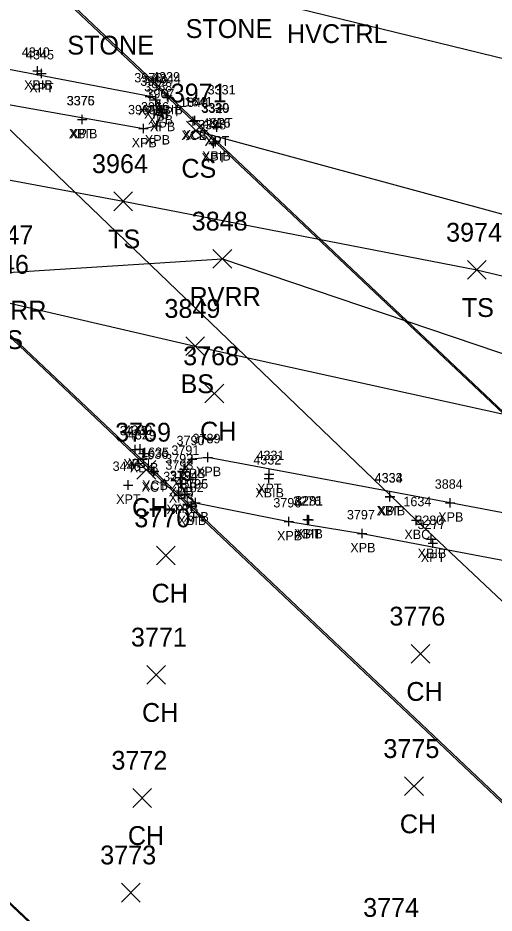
# Model space of a CAD drawing. Extents: x 1647574 to 1652703, y 212895 to 228670.
# Drawn here: x 1648896.4 to 1648947, y 227216.4 to 227311.5 of the extents above; entities that cross this region are included whole.
import ezdxf

# ---------------------------------------------------------------- set-up
doc = ezdxf.new("R2010")
doc.units = 0
for name, color, linetype in [('B_A', 7, 'Continuous'), ('B_I', 7, 'Continuous'), ('B_TIC', 7, 'Continuous'), ('BDC', 7, 'Continuous'), ('BELB', 7, 'Continuous'), ('BSUBM', 7, 'Continuous'), ('C_A', 7, 'Continuous'), ('L_A', 7, 'Continuous'), ('L_I', 7, 'Continuous'), ('L_TIC', 7, 'Continuous'), ('LASF', 7, 'Continuous'), ('LAWE', 7, 'Continuous'), ('LELB', 7, 'Continuous')]:
    doc.layers.add(name, color=color, linetype=linetype)

msp = doc.modelspace()

# ---------------------------------------------------------------- linework, layer by layer
at = {"layer": 'B_TIC'}
for p, q in [((1648898.446, 227305.876), (1648898.522, 227305.876)), ((1648898.857, 227305.593), (1648898.932, 227305.593)), ((1648910.416, 227303.154), (1648910.492, 227303.154)), ((1648911.039, 227302.784), (1648911.114, 227302.784)), ((1648912.274, 227303.242), (1648912.349, 227303.242)), ((1648912.349, 227303.053), (1648912.424, 227303.053)), ((1648911.454, 227302.179), (1648911.53, 227302.179)), ((1648917.888, 227301.873), (1648917.964, 227301.873)), ((1648903.197, 227300.71), (1648903.272, 227300.71)), ((1648903.197, 227300.71), (1648903.272, 227300.71)), ((1648911.684, 227301.467), (1648911.759, 227301.467)), ((1648909.729, 227299.757), (1648909.804, 227299.757)), ((1648911.134, 227300.053), (1648911.21, 227300.053)), ((1648915.01, 227300.535), (1648915.086, 227300.535)), ((1648915.18, 227300.61), (1648915.255, 227300.61)), ((1648917.521, 227299.968), (1648917.596, 227299.968)), ((1648917.529, 227299.911), (1648917.605, 227299.911)), ((1648917.163, 227298.161), (1648917.238, 227298.161)), ((1648917.379, 227298.344), (1648917.455, 227298.344)), ((1648908.838, 227265.651), (1648908.913, 227265.651)), ((1648909.349, 227265.697), (1648909.425, 227265.697)), ((1648909.695, 227265.208), (1648909.77, 227265.208)), ((1648914.907, 227264.6), (1648914.983, 227264.6)), ((1648916.569, 227264.809), (1648916.644, 227264.809)), ((1648914.034, 227263.572), (1648914.109, 227263.572)), ((1648910.793, 227263.155), (1648910.868, 227263.155)), ((1648910.839, 227263.351), (1648910.915, 227263.351)), ((1648913.66, 227262.668), (1648913.735, 227262.668)), ((1648923.086, 227263.025), (1648923.161, 227263.025)), ((1648908.097, 227261.869), (1648908.173, 227261.869)), ((1648913.679, 227261.994), (1648913.754, 227261.994)), ((1648923.04, 227262.55), (1648923.115, 227262.55)), ((1648913.445, 227260.778), (1648913.521, 227260.778)), ((1648914.149, 227260.891), (1648914.225, 227260.891)), ((1648915.258, 227259.994), (1648915.333, 227259.994)), ((1648935.938, 227260.651), (1648936.013, 227260.651)), ((1648935.941, 227260.624), (1648936.016, 227260.624)), ((1648942.333, 227259.976), (1648942.409, 227259.976)), ((1648914.776, 227259.618), (1648914.851, 227259.618)), ((1648925.19, 227257.988), (1648925.265, 227257.988)), ((1648927.18, 227258.193), (1648927.256, 227258.193)), ((1648927.3, 227258.172), (1648927.375, 227258.172)), ((1648938.736, 227258.119), (1648938.812, 227258.119)), ((1648932.986, 227256.718), (1648933.061, 227256.718)), ((1648940.311, 227256.124), (1648940.386, 227256.124)), ((1648940.497, 227255.688), (1648940.573, 227255.688))]:
    msp.add_line(p, q, dxfattribs=at)
for points in [[(1648898.443, 227305.376), (1648898.443, 227306.376)], [(1648897.943, 227305.876), (1648898.943, 227305.876)], [(1648898.353, 227305.593), (1648899.353, 227305.593)], [(1648898.853, 227305.093), (1648898.853, 227306.093)], [(1648910.413, 227302.654), (1648910.413, 227303.654)], [(1648912.27, 227302.742), (1648912.27, 227303.742)], [(1648912.345, 227302.553), (1648912.345, 227303.553)], [(1648909.913, 227303.154), (1648910.913, 227303.154)], [(1648910.535, 227302.784), (1648911.535, 227302.784)], [(1648911.035, 227302.284), (1648911.035, 227303.284)], [(1648911.451, 227301.679), (1648911.451, 227302.679)], [(1648911.77, 227303.242), (1648912.77, 227303.242)], [(1648911.845, 227303.053), (1648912.845, 227303.053)], [(1648910.951, 227302.179), (1648911.951, 227302.179)], [(1648911.68, 227300.967), (1648911.68, 227301.967)], [(1648917.385, 227301.873), (1648918.385, 227301.873)], [(1648917.885, 227301.373), (1648917.885, 227302.373)], [(1648902.693, 227300.71), (1648903.693, 227300.71)], [(1648902.693, 227300.71), (1648903.693, 227300.71)], [(1648903.193, 227300.21), (1648903.193, 227301.21)], [(1648903.193, 227300.21), (1648903.193, 227301.21)], [(1648911.18, 227301.467), (1648912.18, 227301.467)], [(1648915.007, 227300.035), (1648915.007, 227301.035)], [(1648915.176, 227300.11), (1648915.176, 227301.11)], [(1648909.225, 227299.757), (1648910.225, 227299.757)], [(1648909.725, 227299.257), (1648909.725, 227300.257)], [(1648910.631, 227300.053), (1648911.631, 227300.053)], [(1648911.131, 227299.553), (1648911.131, 227300.553)], [(1648914.507, 227300.535), (1648915.507, 227300.535)], [(1648914.676, 227300.61), (1648915.676, 227300.61)], [(1648917.018, 227299.968), (1648918.018, 227299.968)], [(1648917.026, 227299.911), (1648918.026, 227299.911)], [(1648917.518, 227299.468), (1648917.518, 227300.468)], [(1648917.526, 227299.411), (1648917.526, 227300.411)], [(1648917.376, 227297.844), (1648917.376, 227298.844)], [(1648916.659, 227298.161), (1648917.659, 227298.161)], [(1648916.876, 227298.344), (1648917.876, 227298.344)], [(1648917.159, 227297.661), (1648917.159, 227298.661)], [(1648908.334, 227265.651), (1648909.334, 227265.651)], [(1648908.834, 227265.151), (1648908.834, 227266.151)], [(1648908.846, 227265.697), (1648909.846, 227265.697)], [(1648909.346, 227265.197), (1648909.346, 227266.197)], [(1648909.691, 227264.708), (1648909.691, 227265.708)], [(1648909.191, 227265.208), (1648910.191, 227265.208)], [(1648914.404, 227264.6), (1648915.404, 227264.6)], [(1648914.904, 227264.1), (1648914.904, 227265.1)], [(1648916.066, 227264.809), (1648917.066, 227264.809)], [(1648916.566, 227264.309), (1648916.566, 227265.309)], [(1648910.789, 227262.655), (1648910.789, 227263.655)], [(1648910.836, 227262.851), (1648910.836, 227263.851)], [(1648913.53, 227263.572), (1648914.53, 227263.572)], [(1648914.03, 227263.072), (1648914.03, 227264.072)], [(1648923.082, 227262.525), (1648923.082, 227263.525)], [(1648910.289, 227263.155), (1648911.289, 227263.155)], [(1648910.336, 227263.351), (1648911.336, 227263.351)], [(1648913.156, 227262.668), (1648914.156, 227262.668)], [(1648913.656, 227262.168), (1648913.656, 227263.168)], [(1648922.582, 227263.025), (1648923.582, 227263.025)], [(1648923.036, 227262.05), (1648923.036, 227263.05)], [(1648907.594, 227261.869), (1648908.594, 227261.869)], [(1648908.094, 227261.369), (1648908.094, 227262.369)], [(1648913.175, 227261.994), (1648914.175, 227261.994)], [(1648913.675, 227261.494), (1648913.675, 227262.494)], [(1648922.536, 227262.55), (1648923.536, 227262.55)], [(1648912.942, 227260.778), (1648913.942, 227260.778)], [(1648913.442, 227260.278), (1648913.442, 227261.278)], [(1648913.646, 227260.891), (1648914.646, 227260.891)], [(1648914.146, 227260.391), (1648914.146, 227261.391)], [(1648935.934, 227260.151), (1648935.934, 227261.151)], [(1648935.937, 227260.124), (1648935.937, 227261.124)], [(1648914.754, 227259.994), (1648915.754, 227259.994)], [(1648914.772, 227259.118), (1648914.772, 227260.118)], [(1648915.254, 227259.494), (1648915.254, 227260.494)], [(1648935.434, 227260.651), (1648936.434, 227260.651)], [(1648935.437, 227260.624), (1648936.437, 227260.624)], [(1648941.83, 227259.976), (1648942.83, 227259.976)], [(1648942.33, 227259.476), (1648942.33, 227260.476)], [(1648914.272, 227259.618), (1648915.272, 227259.618)], [(1648924.686, 227257.988), (1648925.686, 227257.988)], [(1648925.186, 227257.488), (1648925.186, 227258.488)], [(1648926.677, 227258.193), (1648927.677, 227258.193)], [(1648926.796, 227258.172), (1648927.796, 227258.172)], [(1648927.177, 227257.693), (1648927.177, 227258.693)], [(1648927.296, 227257.672), (1648927.296, 227258.672)], [(1648938.233, 227258.119), (1648939.233, 227258.119)], [(1648938.733, 227257.619), (1648938.733, 227258.619)], [(1648932.982, 227256.218), (1648932.982, 227257.218)], [(1648932.482, 227256.718), (1648933.482, 227256.718)], [(1648939.807, 227256.124), (1648940.807, 227256.124)], [(1648940.307, 227255.624), (1648940.307, 227256.624)], [(1648940.494, 227255.188), (1648940.494, 227256.188)], [(1648939.994, 227255.688), (1648940.994, 227255.688)]]:
    msp.add_lwpolyline(points, dxfattribs=at)
at = {"layer": 'BDC'}
for points in [[(1648705.852, 227396.154), (1648745.059, 227359.411), (1648787.916, 227318.711), (1648830.863, 227278.3), (1648888.33, 227224.067), (1648945.958, 227169.85), (1649010.577, 227108.866), (1649057.241, 227064.803), (1649099.962, 227024.603)], [(1648705.902, 227396.256), (1648745.142, 227359.215), (1648788.072, 227318.717), (1648831.078, 227278.232), (1648888.572, 227223.976), (1648945.897, 227169.932), (1649010.764, 227109.119), (1649057.374, 227064.845), (1649100.019, 227024.673)], [(1649190.777, 226999.084), (1649140.468, 227046.558), (1649090.33, 227093.733), (1649025.71, 227154.751), (1648968.186, 227208.898), (1648910.789, 227263.155), (1648860.431, 227310.794), (1648808.664, 227359.741)], [(1649190.944, 226999.114), (1649140.59, 227046.719), (1649090.397, 227093.864), (1649025.741, 227154.791), (1648968.355, 227208.988), (1648910.836, 227263.351), (1648860.59, 227310.809), (1648808.767, 227359.651)], [(1649243.4, 226991.008), (1649194.892, 227036.57), (1649144.766, 227083.811), (1649080.187, 227144.73), (1649023.114, 227198.758), (1648965.385, 227253.071), (1648915.007, 227300.535), (1648862.79, 227349.772)], [(1649243.526, 226991.095), (1649195.071, 227036.681), (1649144.945, 227083.846), (1649080.275, 227144.791), (1649023.25, 227198.713), (1648965.389, 227253.216), (1648915.176, 227300.61), (1648862.963, 227349.863)]]:
    msp.add_lwpolyline(points, dxfattribs=at)
at = {"layer": 'BELB'}
msp.add_lwpolyline([(1649218.046, 226994.506), (1649168.124, 227041.655), (1649117.675, 227088.79), (1649053.801, 227149.566), (1648996.598, 227203.697), (1648938.733, 227258.119), (1648889.571, 227305.276), (1648838.072, 227353.54)], dxfattribs=at)
at = {"layer": 'BSUBM'}
for points in [[(1648869.587, 227310.945), (1648865.798, 227311.358), (1648865.089, 227311.327), (1648864.247, 227309.806), (1648864.506, 227308.492), (1648865.002, 227308.106), (1648866.386, 227307.449), (1648909.725, 227299.757), (1648911.131, 227300.053), (1648911.68, 227301.467), (1648911.451, 227302.179), (1648911.035, 227302.784), (1648910.413, 227303.154), (1648869.587, 227310.945)], [(1648916.566, 227264.809), (1648914.904, 227264.6), (1648914.03, 227263.572), (1648913.656, 227262.668), (1648913.675, 227261.994), (1648914.146, 227260.891), (1648915.254, 227259.994), (1648925.186, 227257.988), (1648932.982, 227256.718), (1648949.038, 227253.686), (1648959.595, 227251.665), (1648961.024, 227251.696), (1648962.063, 227252.417), (1648962.575, 227253.5), (1648962.609, 227255.038), (1648961.798, 227256.037), (1648960.449, 227256.533), (1648942.33, 227259.976), (1648916.566, 227264.809)]]:
    msp.add_lwpolyline(points, dxfattribs=at)
at = {"layer": 'L_TIC'}
for points in [[(1648914.306, 227298.521), (1648916.306, 227300.521)], [(1648916.306, 227298.521), (1648914.306, 227300.521)], [(1648906.545, 227291.016), (1648908.545, 227293.016)], [(1648908.545, 227291.016), (1648906.545, 227293.016)], [(1648917.106, 227284.909), (1648919.106, 227286.909)], [(1648919.106, 227284.909), (1648917.106, 227286.909)], [(1648944.167, 227283.729), (1648946.167, 227285.729)], [(1648946.167, 227283.729), (1648944.167, 227285.729)], [(1648914.213, 227275.631), (1648916.213, 227277.631)], [(1648916.213, 227275.631), (1648914.213, 227277.631)], [(1648916.248, 227270.596), (1648918.248, 227272.596)], [(1648918.248, 227270.596), (1648916.248, 227272.596)], [(1648909.013, 227262.483), (1648911.013, 227264.483)], [(1648911.013, 227262.483), (1648909.013, 227264.483)], [(1648911.089, 227253.38), (1648913.089, 227255.38)], [(1648913.089, 227253.38), (1648911.089, 227255.38)], [(1648938.189, 227242.938), (1648940.189, 227244.938)], [(1648940.189, 227242.938), (1648938.189, 227244.938)], [(1648910.073, 227240.706), (1648912.073, 227242.706)], [(1648912.073, 227240.706), (1648910.073, 227242.706)], [(1648937.496, 227228.866), (1648939.496, 227230.866)], [(1648939.496, 227228.866), (1648937.496, 227230.866)], [(1648908.569, 227227.622), (1648910.569, 227229.622)], [(1648910.569, 227227.622), (1648908.569, 227229.622)], [(1648907.375, 227217.559), (1648909.375, 227219.559)], [(1648909.375, 227217.559), (1648907.375, 227219.559)]]:
    msp.add_lwpolyline(points, dxfattribs=at)
at = {"layer": 'LASF'}
msp.add_lwpolyline([(1648650.222, 227380.955), (1648665.187, 227366.232), (1648704.752, 227348.923), (1648726.242, 227345.003), (1648748.022, 227340.215), (1648778.691, 227335.468), (1648795.179, 227328.09), (1648829.721, 227323.979), (1648869.231, 227314.255), (1648889.736, 227315.356), (1648906.07, 227312.609), (1648918.662, 227314.372), (1648951.491, 227306.349), (1648977.567, 227292.251), (1648987.29, 227278.611), (1648987.249, 227274.742)], dxfattribs=at)
at = {"layer": 'LAWE'}
msp.add_lwpolyline([(1648523.618, 227464.437), (1648558.315, 227431.33), (1648577.139, 227410.096), (1648589.542, 227390.215), (1648614.463, 227367.163), (1648643.493, 227349.685), (1648671.906, 227332.593), (1648697.558, 227323.897), (1648718.58, 227316.224), (1648748.456, 227309.789), (1648786.397, 227302.267), (1648830.69, 227294.491), (1648864.898, 227288.599), (1648895.304, 227284.453), (1648918.106, 227285.909), (1648972.006, 227267.699), (1649004.518, 227260.095), (1649036.332, 227254.751), (1649067.753, 227244.931), (1649099.556, 227239.623), (1649133.345, 227233.557), (1649168.721, 227227.534), (1649200.785, 227221.115), (1649219.753, 227218.741)], dxfattribs=at)
at = {"layer": 'LELB'}
for points in [[(1648624.782, 227367.39), (1648661.563, 227343.255), (1648687.991, 227330.789), (1648710.881, 227324.59), (1648732.4, 227320.11), (1648758.291, 227314.941), (1648781.981, 227308.526), (1648826.946, 227303.501), (1648863.734, 227300.174), (1648907.545, 227292.016), (1648945.167, 227284.729), (1648987.249, 227274.742), (1649006.387, 227273.993), (1649032.821, 227270.544), (1649043.18, 227273.015), (1649036.389, 227297.452)], [(1648785.473, 227299.553), (1648829.465, 227290.758), (1648865.217, 227283.832), (1648894.895, 227281.32), (1648915.213, 227276.631), (1648970.743, 227264.412), (1649004.316, 227256.615), (1649035.751, 227252.607), (1649067.455, 227243.568), (1649099.248, 227238.183), (1649133.364, 227231.231), (1649168.074, 227224.491), (1649200.359, 227218.768), (1649219.225, 227216.606)], [(1648915.306, 227299.521), (1648953.159, 227289.218), (1648987.29, 227278.611)]]:
    msp.add_lwpolyline(points, dxfattribs=at)

# ---------------------------------------------------------------- texts
at = {"layer": 'B_A'}
for s, p in [('XBIB', (1648897.014, 227303.876)), ('XPT', (1648897.574, 227303.593)), ('XPB', (1648909.149, 227301.154)), ('XPB', (1648909.771, 227300.784)), ('XBIB', (1648910.841, 227301.242)), ('XPT', (1648911.066, 227301.053)), ('XPB', (1648910.187, 227300.179)), ('XPT', (1648916.605, 227299.873)), ('XBIB', (1648901.764, 227298.71)), ('XPT', (1648901.914, 227298.71)), ('XPB', (1648910.417, 227299.467)), ('XPB', (1648908.461, 227297.757)), ('XPB', (1648909.867, 227298.053)), ('XCB', (1648913.743, 227298.535)), ('XCT', (1648913.897, 227298.61)), ('XPT', (1648916.238, 227297.968)), ('XPT', (1648916.246, 227297.911)), ('XPT', (1648915.88, 227296.161)), ('XBIB', (1648915.947, 227296.344)), ('XPT', (1648907.555, 227263.651)), ('XPT', (1648908.066, 227263.697)), ('XBIB', (1648908.262, 227263.208)), ('XPB', (1648913.64, 227262.6)), ('XPB', (1648915.302, 227262.809)), ('XPB', (1648912.766, 227261.572)), ('XCT', (1648909.51, 227261.155)), ('XCB', (1648909.572, 227261.351)), ('XPB', (1648912.392, 227260.668)), ('XPT', (1648921.803, 227261.025)), ('XPT', (1648906.814, 227259.869)), ('XPB', (1648912.411, 227259.994)), ('XBIB', (1648921.607, 227260.55)), ('XPT', (1648912.162, 227258.778)), ('XPB', (1648912.882, 227258.891)), ('XPB', (1648913.99, 227257.994)), ('XBIB', (1648934.505, 227258.651)), ('XPT', (1648934.658, 227258.624)), ('XPB', (1648941.066, 227257.976)), ('XBIB', (1648913.343, 227257.618)), ('XPB', (1648923.922, 227255.988)), ('XBIB', (1648925.748, 227256.193)), ('XPT', (1648926.017, 227256.172)), ('XBC', (1648937.469, 227256.119)), ('XPB', (1648931.719, 227254.718)), ('XBIB', (1648938.878, 227254.124)), ('XPT', (1648939.214, 227253.688))]:
    msp.add_text(s, height=1, dxfattribs=at).set_placement(p)
at = {"layer": 'B_I'}
for s, p in [('4340', (1648896.77, 227307.376)), ('4345', (1648897.224, 227307.093)), ('3970', (1648908.74, 227304.654)), ('4339', (1648910.636, 227304.742)), ('4344', (1648910.716, 227304.553)), ('3969', (1648909.378, 227304.284)), ('3968', (1648909.797, 227303.679)), ('3967', (1648910.027, 227302.967)), ('3331', (1648916.538, 227303.373)), ('3376', (1648901.536, 227302.21)), ('3375', (1648901.563, 227302.21)), ('3966', (1648909.449, 227301.553)), ('1640', (1648913.593, 227302.035)), ('1641', (1648914.09, 227302.11)), ('3965', (1648908.072, 227301.257)), ('3330', (1648915.844, 227301.468)), ('3329', (1648915.892, 227301.411)), ('3328', (1648915.53, 227299.661)), ('4316', (1648916.002, 227299.844)), ('3445', (1648907.205, 227267.151)), ('4330', (1648907.672, 227267.197)), ('4329', (1648908.057, 227266.708)), ('3789', (1648914.932, 227266.309)), ('3790', (1648913.231, 227266.1)), ('1636', (1648909.392, 227264.655)), ('1635', (1648909.466, 227264.851)), ('3791', (1648912.684, 227265.072)), ('4331', (1648921.736, 227264.525)), ('3792', (1648912.026, 227264.168)), ('3793', (1648912.045, 227263.494)), ('4332', (1648921.407, 227264.05)), ('3446', (1648906.436, 227263.369)), ('3275', (1648911.812, 227262.278)), ('3794', (1648912.516, 227262.391)), ('4333', (1648934.305, 227262.151)), ('4334', (1648934.307, 227262.124)), ('3282', (1648913.142, 227261.118)), ('3795', (1648913.624, 227261.494)), ('3884', (1648940.7, 227261.476)), ('3276', (1648925.639, 227259.672)), ('3281', (1648925.83, 227259.693)), ('3796', (1648923.529, 227259.488)), ('1634', (1648937.363, 227259.619)), ('3797', (1648931.353, 227258.218)), ('3280', (1648938.634, 227257.624)), ('3277', (1648938.864, 227257.188))]:
    msp.add_text(s, height=1, dxfattribs=at).set_placement(p)
at = {"layer": 'C_A'}
msp.add_text('HVCTRL', height=2, dxfattribs=at).set_placement((1648924.979, 227308.834))
at = {"layer": 'L_A'}
for s, p in [('STONE', (1648914.206, 227309.372)), ('STONE', (1648901.613, 227307.609)), ('CS', (1648913.747, 227294.521)), ('TS', (1648905.954, 227287.016)), ('RVRR', (1648914.617, 227280.909)), ('TS', (1648943.576, 227279.729)), ('RVRR', (1648891.816, 227279.453)), ('BS', (1648893.336, 227276.32)), ('BS', (1648913.654, 227271.631)), ('CH', (1648915.736, 227266.596)), ('CH', (1648908.501, 227258.483)), ('CH', (1648910.577, 227249.38)), ('CH', (1648937.677, 227238.938)), ('CH', (1648909.561, 227236.706)), ('CH', (1648936.984, 227224.866)), ('CH', (1648908.057, 227223.622))]:
    msp.add_text(s, height=2, dxfattribs=at).set_placement(p)
at = {"layer": 'L_I'}
for s, p in [('3971', (1648912.614, 227302.521)), ('3964', (1648904.238, 227295.016)), ('3848', (1648914.846, 227288.909)), ('3847', (1648892.044, 227287.453)), ('3974', (1648941.907, 227287.729)), ('3846', (1648891.58, 227284.32)), ('3849', (1648911.945, 227279.631)), ('3768', (1648913.941, 227274.596)), ('3769', (1648906.698, 227266.483)), ('3770', (1648908.743, 227257.38)), ('3776', (1648935.874, 227246.938)), ('3771', (1648908.38, 227244.706)), ('3775', (1648935.236, 227232.866)), ('3772', (1648906.309, 227231.622)), ('3773', (1648905.115, 227221.559)), ('3774', (1648933.081, 227215.981))]:
    msp.add_text(s, height=2, dxfattribs=at).set_placement(p)

doc.saveas('drawing.dxf')
